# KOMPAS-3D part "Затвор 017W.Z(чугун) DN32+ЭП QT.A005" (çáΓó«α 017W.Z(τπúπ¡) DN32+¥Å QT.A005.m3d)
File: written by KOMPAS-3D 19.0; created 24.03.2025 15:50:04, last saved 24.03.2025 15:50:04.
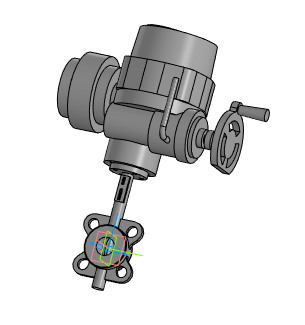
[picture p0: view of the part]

Document properties: Полное имя файла: Затвор 017W.Z(чугун) DN32+ЭП QT.A005.a3d

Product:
- Part/product: Затвор 017W.Z(чугун) DN32+ЭП QT.A005
    Масса: 37.5755

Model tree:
1. Операция без истории:1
